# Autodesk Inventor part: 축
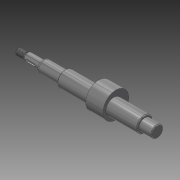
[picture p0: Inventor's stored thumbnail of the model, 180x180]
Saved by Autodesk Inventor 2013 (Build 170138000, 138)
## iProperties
Created: 2015-12
Part Number: 축
Document SubType Name: Modeling
Designer: mdu
Density: 7.86 g/cm^3
Material: 강철, 연강
Mass: 421.834 g
Surface Area: 119.066 cm^2
Volume: 53.6685 cm^3
Author: mdu
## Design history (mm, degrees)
sketch "스케치1"
  geometry: L1 (62, 100.9)-(62, 67.1) reference; L2 (51, 101.2)-(51, 84) reference; L3 (-51, 84)-(-51, 101.2) reference; L4 (-62, 67.1)-(-62, 100.9) reference; L5 (-51.6, 91.5)-(-61.4, 91.5) reference; L6 (51.6, 91.5)-(61.4, 91.5) reference; L7 (67, 84)-(-111, 84); L8 (-77, 64.201)-(-77, 103.799) reference; L9 (67, 84)-(67, 91.5); L10 (67, 91.5)-(51, 91.5); L11 (51, 91.5)-(51, 94); L12 (51, 94)-(-51, 94); L13 (-51, 94)-(-51, 91.5); L14 (-51, 91.5)-(-79, 91.5); L15 (-79, 91.5)-(-79, 89); L16 (-79, 89)-(-99, 89); L17 (-99, 89)-(-99, 87); L18 (-100.5, 88)-(-111, 88); L19 (-111, 88)-(-111, 84); L20 (-99, 87)-(-100.5, 87); L21 (-100.5, 87)-(-100.5, 88); 2 further points
  constraints: 32 end point, 7 parallel, 6 point on line, 5 perpendicular, 2 collinear, 2 horizontal, 1 midpoint, 4 other
  dimensions: "d0" = 5 distance from line of L7.start L1; "d2" = 2 distance between parallel lines of L15 L8; "d3" = 20 diameter of L12 L7; "d4" = 10 diameter of L16 L7; "d5" = 1.5 distance of L17.end L20.end; "d6" = 6 diameter of L20 L7; "d7" = 20 distance of L15.end L16.end; "d8" = 12 distance between parallel lines of L17 L19; "d9" = 8 diameter of L18 L7
revolve "회전1" sketch "스케치1" stored, may be unused: angle "d10" = 90 deg
sketch "스케치2"
  geometry: C1 r 10 at (84, 0) reference; C2 r 10 at (84, 0) reference; C3 r 16.5 at (87, 0); 1 further point
  constraints: 1 centre point, 1 horizontal alignment
  dimensions: "d11" = 33 diameter of C3; "d12" = 3 distance of C3.centre C1.centre
extrude "돌출1" join sketch "스케치2" stored distance "d13" = 22; taper "d14" = 0 deg
chamfer "모따기1" distance "d15" = 1; stored, may be unused: second distance "d16" = 2, angle "d17" = 45 deg
feature "스레드1" dims "d18" = 10, "d19" = 0
node "작업 평면1"
sketch "스케치3"
  geometry: L1 (-5.5, -1.5)-(3.5, -1.5); L2 (3.5, 1.5)-(-5.5, 1.5); L3 (-10, -4)-(-10, 4) reference; A1 r 1.5 centre (3.5, 0) between (3.5, -1.5) and (3.5, 1.5); A2 r 1.5 centre (-5.5, 0) between (-5.5, 1.5) and (-5.5, -1.5); 2 further points
  constraints: 4 end point, 4 point on circle, 4 tangent, 2 centre point, 1 horizontal, 1 horizontal alignment, 1 midpoint, 1 parallel
  dimensions: "d20" = 3 distance between parallel lines of L1 L2; "d21" = 12 dimension on A1 A2; "d22" = 3 distance edge to line of A2 L3
extrude "돌출2" cut sketch "스케치3" distance "d23" = 1.8; taper "d24" = 0 deg
fillet "모깎기1" dims "d25" = 0.3
fillet "모깎기2" dims "d26" = 3
node "솔리드1"
node "참조1"
node "참조2"
node "참조3"
node "참조4"
node "참조5"
node "투영된 루프1"
